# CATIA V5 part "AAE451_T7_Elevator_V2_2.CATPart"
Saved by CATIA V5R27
Part number: Elevator
Bounding box of the stored display mesh (mm): x 0 to 69.698, y -12.436 to 0.05, z 0 to 229.955
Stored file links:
  W:\AAE 451\AAE451_T7_TailAssembly_V2\AAE451_T7_Elevator_V2_2.CATPart
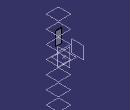
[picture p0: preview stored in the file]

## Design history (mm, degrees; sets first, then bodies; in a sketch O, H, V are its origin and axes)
Set1 "GeometryFromExcel"
  Point1: (1, 0.001, 0)
  Point2: (0.95, 0.0067, 0)
  Point3: (0.9, 0.0121, 0)
  Point4: (0.8, 0.0219, 0)
  Point5: (0.7, 0.0305, 0)
  Point6: (0.6, 0.038, 0)
  Point7: (0.5, 0.0441, 0)
  Point8: (0.4, 0.0484, 0)
  Point9: (0.3, 0.05, 0)
  Point10: (0.25, 0.0495, 0)
  Point11: (0.2, 0.0478, 0)
  Point12: (0.15, 0.0445, 0)
  Point13: (0.1, 0.039, 0)
  Point14: (0.075, 0.035, 0)
  Point15: (0.05, 0.0296, 0)
  Point16: (0.025, 0.0218, 0)
  Point17: (0.0125, 0.0158, 0)
  Point18: (0, 0, 0)
  Point19: (0.0125, -0.0158, 0)
  Point20: (0.025, -0.0218, 0)
  Point21: (0.05, -0.0296, 0)
  Point22: (0.075, -0.035, 0)
  Point23: (0.1, -0.039, 0)
  Point24: (0.15, -0.0445, 0)
  Point25: (0.2, -0.0478, 0)
  Point26: (0.25, -0.0495, 0)
  Point27: (0.3, -0.05, 0)
  Point28: (0.4, -0.0484, 0)
  Point29: (0.5, -0.0441, 0)
  Point30: (0.6, -0.038, 0)
  Point31: (0.7, -0.0305, 0)
  Point32: (0.8, -0.0219, 0)
  Point33: (0.9, -0.0121, 0)
  Point34: (0.95, -0.0067, 0)
  Point35: (1, -0.001, 0)
  Point36: (1, 0.001, 0)
  Point37: (0.95, 0.0067, 0)
  Point38: (0.9, 0.0121, 0)
  Point39: (0.8, 0.0219, 0)
  Point40: (0.7, 0.0305, 0)
  Point41: (0.6, 0.038, 0)
  Point42: (0.5, 0.0441, 0)
  Point43: (0.4, 0.0484, 0)
  Point44: (0.3, 0.05, 0)
  Point45: (0.25, 0.0495, 0)
  Point46: (0.2, 0.0478, 0)
  Point47: (0.15, 0.0445, 0)
  Point48: (0.1, 0.039, 0)
  Point49: (0.075, 0.035, 0)
  Point50: (0.05, 0.0296, 0)
  Point51: (0.025, 0.0218, 0)
  Point52: (0.0125, 0.0158, 0)
  Point53: (0, 0, 0)
  Point54: (0.0125, -0.0158, 0)
  Point55: (0.025, -0.0218, 0)
  Point56: (0.05, -0.0296, 0)
  Point57: (0.075, -0.035, 0)
  Point58: (0.1, -0.039, 0)
  Point59: (0.15, -0.0445, 0)
  Point60: (0.2, -0.0478, 0)
  Point61: (0.25, -0.0495, 0)
  Point62: (0.3, -0.05, 0)
  Point63: (0.4, -0.0484, 0)
  Point64: (0.5, -0.0441, 0)
  Point65: (0.6, -0.038, 0)
  Point66: (0.7, -0.0305, 0)
  Point67: (0.8, -0.0219, 0)
  Point68: (0.9, -0.0121, 0)
  Point69: (0.95, -0.0067, 0)
  Point70: (1, -0.001, 0)
  Curve1: Elements (Point36; Point37; Point38; Point39; Point40; Point41; Point42; Point43; Point44; Point45; Point46; Point47; Point48; Point49; Point50; Point51; Point52; Point53; Point54; Point55; Point56; Point57; Point58; Point59; Point60; Point61; Point62; Point63; Point64; Point65; Point66; Point67; Point68; Point69; Point70)
  Sketch1 on xy-plane, origin (0, 0, 0), H (1, 0, 0), V (0, 1, 0)
    projected curve E1 from edge of Curve1
    point P1 (1, 0.0011)
    line L1 (1, 0.0011) -> (1, -0.001)
    point P3 (1, 0.001)
    point P4 (1, -0.001)
    reference projected point E2 (1, 0.001) from Point1
    reference projected point E3 (1, -0.001) from Point35
    coincidence: P3 E2, P4 E3, P1 P3
Body1 (main body)
  Pad1: profile Sketch1, direction (0, 0, 1), length 1.5215, mirrored extent
  Scaling1: Reference Point40, Ratio 230, ToTransfor Pad1
  Plane1: type Offset, RefPlane yz-plane, Offset 120, reversed
  Sketch2 on xy-plane, origin (0, 0, 0), H (1, 0, 0), V (0, 1, 0)
    reference projected line E1 (69.6979, -7.2245) -> (69.698, -6.7499) from edge [face of Pad1 from Sketch1.L1 | end face of Pad1]
    line L1 (13.6994, -1.0636) -> (13.6965, -12.9194)
    projected curve E2 from edge [face of Pad1 from Sketch1.E1 | end face of Pad1]
    projected curve E3 from edge [face of Pad1 from Sketch1.E1 | end face of Pad1]
    distance E1 L1 = 56
  Pocket1: profile Sketch2, direction (0, 0, -1), through (limit type 3), opposite side through (limit type 3)
  Fillet1: radius 5, on edge [face of Pad1 from Sketch1.E1 | face of Pocket1 from Sketch2.L1]; edge [face of Pocket1 from Sketch2.L1 | face of Pad1 from Sketch1.E1]
  Sketch3 on zx-plane, origin (0, 0, 0), H (-1, 0, 0), V (0, 0, 1)
    line L1 (-135.4649, -344.945) -> (50.2623, -344.945)
    line L2 (50.2623, -344.945) -> (50.2623, -349.945)
    line L3 (50.2623, -349.945) -> (-135.4649, -349.945)
    line L4 (-135.4649, -349.945) -> (-135.4649, -344.945)
    line L5 (-146.4826, 349.945) -> (56.5582, 349.945)
    line L6 (56.5582, 349.945) -> (56.5582, 344.945)
    line L7 (56.5582, 344.945) -> (-146.4826, 344.945)
    line L8 (-146.4826, 344.945) -> (-146.4826, 349.945)
    reference projected line E1 (-69.7, 349.945) -> (160.3, 349.945) from edge [face of Pad1 from Sketch1.E1 | end face of Pad1]
    reference projected line E2 (-69.7, -349.945) -> (160.3, -349.945) from edge [start face of Pad1 | face of Pad1 from Sketch1.E1]
    distance L7 L5 = 5
    horizontal: L1 H, L3 H, L5 H, L7 H
    vertical: L2 V, L4 V, L6 V, L8 V
    coincidence: L5 E1, L3 E2
    symmetry: L7 L1 H
  Pocket2: profile Sketch3, direction (0, -1, 0), through (limit type 3)
  Sketch4 on face of Pocket1 from Sketch2.L1, origin (13.6996, -0.0033, 0), H (-0.0002, -1, 0), V (0, 0, 1)
    line L1 (6.4867, 8) -> (7.4867, 8)
    line L2 (7.4867, 8) -> (7.4867, -8)
    line L3 (7.4867, -8) -> (6.4867, -8)
    line L4 (6.4867, -8) -> (6.4867, 8)
    construction line L5 (6.9867, 7.1913) -> (6.9867, -6.7162)
    reference projected line E1 (1.5418, 344.945) -> (1.5418, -344.945) from edge [face of Pad1 from Sketch1.E1 | face of Fillet1]
    reference projected line E2 (12.4317, 344.945) -> (12.4317, -344.945) from edge [face of Fillet1 | face of Pad1 from Sketch1.E1]
    distance L4 L2 = 1
    distance L1 L3 = 16
    horizontal: L1 H, L3 H
    vertical: L2 V, L4 V
    symmetry: L3 L1 H, L4 L2 L5, E1 E2 L5
  Pocket3: profile Sketch4, direction (1, -0.0002, 0), length 13.7
  RectPattern1: of Pocket3, direction 1 instances 2, spacing 230, along zx-plane
  Mirror1: of RectPattern1, about xy-plane
  Plane2: type Offset, RefPlane face of Pocket2 from Sketch3.L7, Offset 0, reversed
  Plane3: type Offset, RefPlane face of Pocket2 from Sketch3.L1, Offset 0, reversed
  Plane4: type Offset, RefPlane Plane3, Offset 114.98
  Plane5: type Offset, RefPlane Plane4, Offset 114.98
  Plane6: type Offset, RefPlane Plane5, Offset 114.98
  Plane7: type Offset, RefPlane Plane6, Offset 114.98
  Plane8: type Offset, RefPlane Plane7, Offset 114.98
  Split1: SplitPlane Plane7
  Split2: SplitPlane Plane8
